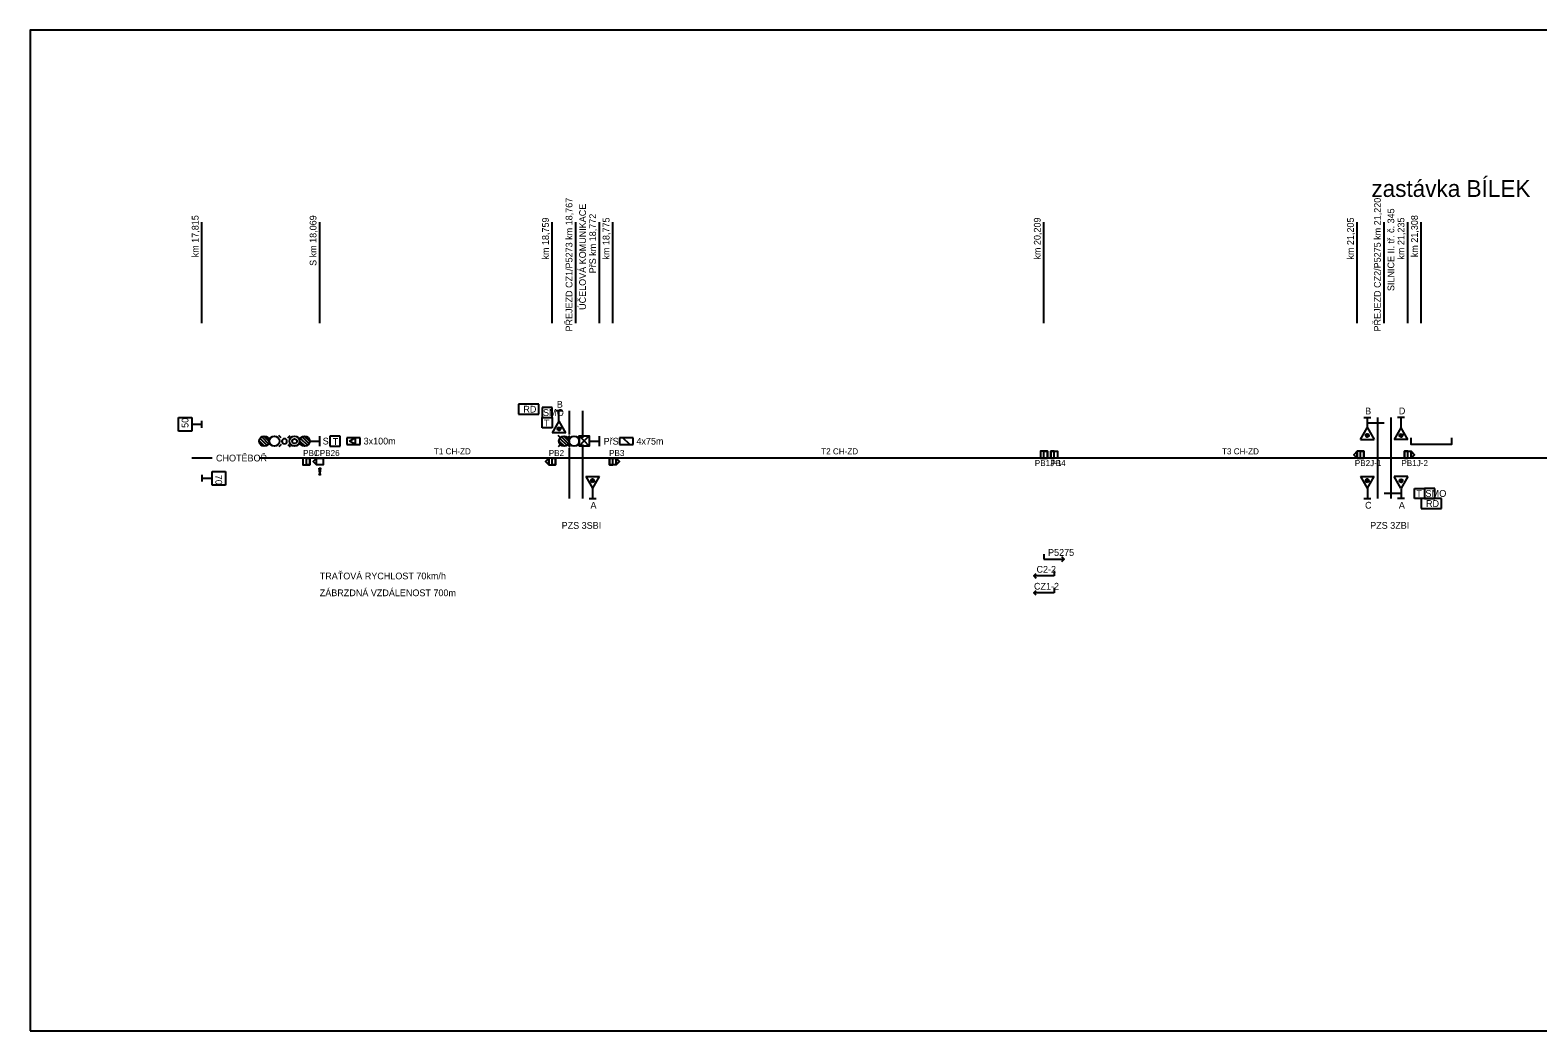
# Model space of a CAD drawing. Extents: x 2343 to 7744, y -5880 to 2050.
# Drawn here: x 4570 to 5017.6, y -5880 to -5583 of the extents above; entities that cross this region are included whole.
import ezdxf

# ---------------------------------------------------------------- set-up
doc = ezdxf.new("R2010")
doc.units = 0
for name, color, linetype in [('LISTY', 7, 'Continuous'), ('NAVRHOVANÉ', 7, 'Continuous'), ('Vrstva 1', 7, 'Continuous'), ('Vrstva 50', 7, 'Continuous'), ('VTO', 7, 'Continuous')]:
    doc.layers.add(name, color=color, linetype=linetype)

# ---------------------------------------------------------------- blocks, each defined once
blk = doc.blocks.new('SB113')
at = {"layer": 'Vrstva 1'}
for points in [[(10, 0), (-10, 0), (-10, -20), (10, -20)], [(0, 0), (10, 0), (10, -20), (0, -20)]]:
    blk.add_lwpolyline(points, close=True, dxfattribs=at)
blk = doc.blocks.new('O10')
at = {"layer": 'Vrstva 1'}
for p, q in [((3, 3), (-3, 3)), ((-3, 3), (-3, 0)), ((-3, 0), (3, 0)), ((3, 0), (3, 3))]:
    blk.add_line(p, q, dxfattribs=at)
blk.add_text('RD', height=2, dxfattribs=at).set_placement((-1.57, 0.503))
blk = doc.blocks.new('O9')
for p, q in [((1.512, 3.012), (-1.488, 3.012)), ((-1.488, 3.012), (-1.488, 0.012)), ((-1.488, 0.012), (1.512, 0.012)), ((1.512, 0.012), (1.512, 3.012))]:
    blk.add_line(p, q)
blk.add_text('T', height=2).set_placement((-0.664, 0.423))
blk = doc.blocks.new('P38')
at = {"layer": 'Vrstva 1'}
for p, q in [((0, 15), (0, 0)), ((0, 0), (60, 0))]:
    blk.add_line(p, q, dxfattribs=at)
blk.add_lwpolyline([(52.9, -7.1), (60, 0), (52.9, 7.1)], dxfattribs=at)
blk = doc.blocks.new('NS14')
for p, q in [((0.1, 18), (-1.5, 16.4)), ((0.8, 17.7), (-1.2, 15.7)), ((1.3, 17.25), (-0.8, 15.2)), ((1.5, 16.6), (-0.1, 15)), ((-1, 11.5), (-1.7, 12.2)), ((-1, 9.5), (-1.7, 8.8)), ((1, 11.5), (1.7, 12.2)), ((1, 9.5), (1.7, 8.8)), ((0.1, 6), (-1.5, 4.4)), ((0.8, 5.7), (-1.2, 3.7)), ((1.3, 5.25), (-0.8, 3.2)), ((1.5, 4.6), (-0.1, 3)), ((-1.5, 0), (1.5, 0)), ((0, 3), (0, 0))]:
    blk.add_line(p, q)
for centre, radius in [((0, 16.5), 1.5), ((0, 13.5), 1.5), ((0, 7.5), 1.5), ((0, 4.5), 1.5), ((0, 7.5), 0.7)]:
    blk.add_circle(centre, radius)
for start, end in [(0, 180), (180, 0)]:
    blk.add_arc((0, 10.5), 0.75, start, end)
blk = doc.blocks.new('NS44')
at = {"layer": 'Vrstva 1'}
blk.add_lwpolyline([(-3.8, 40), (3.7, 40), (0, 10)], close=True, dxfattribs=at)
blk.add_circle((0, 3.7), 3.75, dxfattribs=at)
blk = doc.blocks.new('U7')
at = {"layer": 'Vrstva 1'}
for p, q in [((-1, 4), (-1, 0)), ((1, 4), (-1, 4)), ((-1, 0), (1, 0)), ((-0.971, 1.411), (0.029, 3.143)), ((-0.971, 1.411), (1.029, 1.411)), ((0.029, 3.143), (1.029, 1.411)), ((1, 0), (1, 4))]:
    blk.add_line(p, q, dxfattribs=at)
blk = doc.blocks.new('U3')
at = {"layer": 'Vrstva 1'}
for p, q in [((1, 4), (-1, 4)), ((-1, 4), (-1, 0)), ((-1, 1), (1, 3)), ((-1, 0), (1, 0)), ((1, 0), (1, 4))]:
    blk.add_line(p, q, dxfattribs=at)
blk = doc.blocks.new('NS30')
at = {"layer": 'Vrstva 1'}
for p, q in [((-1.499, 3.001), (0, 1.5)), ((1.499, 3.001), (-1.499, 3.001)), ((-1.499, 0), (0, 1.5)), ((1.499, 0), (-1.499, 0)), ((0, 1.5), (1.499, 3.001)), ((0, 1.5), (1.499, 0))]:
    blk.add_line(p, q, dxfattribs=at)
blk.add_lwpolyline([(-1.499, 3.001), (1.499, 3.001), (1.499, 0), (-1.499, 0)], close=True, dxfattribs=at)

msp = doc.modelspace()

# ---------------------------------------------------------------- linework, layer by layer
for p, q in [((4621, -5670), (4621, -5640)), ((4725, -5670), (4725, -5640)), ((4743, -5670), (4743, -5640)), ((4871, -5670), (4871, -5640)), ((4964, -5670), (4964, -5640)), ((4979, -5670), (4979, -5640)), ((4983, -5670), (4983, -5640)), ((4614, -5702), (4614, -5698)), ((4614, -5698), (4618, -5698)), ((4618, -5698), (4618, -5702)), ((4725, -5695), (4722, -5695)), ((4722, -5695), (4722, -5698)), ((4722, -5698), (4725, -5698)), ((4725, -5698), (4725, -5695)), ((4728, -5696), (4726, -5696)), ((4727, -5699.01), (4727, -5696)), ((4730, -5696), (4730, -5703)), ((4734, -5696), (4734, -5704)), ((4970, -5698), (4970, -5722)), ((4974, -5698), (4974, -5722)), ((4978, -5698), (4976, -5698)), ((4977, -5701.01), (4977, -5698)), ((4618, -5702), (4614, -5702)), ((4621, -5700), (4618, -5700)), ((4621, -5701), (4621, -5699)), ((4726.98, -5699.03), (4725, -5702.52)), ((4729, -5702.52), (4725, -5702.52)), ((4726.52, -5701.26), (4727.05, -5701.79)), ((4726.7, -5700.91), (4727.4, -5701.61)), ((4729, -5702.52), (4727.02, -5699.04)), ((4727.13, -5700.8), (4727.5, -5701.18)), ((4976.98, -5701.03), (4975, -5704.52)), ((4979, -5704.52), (4977.02, -5701.04)), ((4730, -5707), (4730, -5722)), ((4734, -5706), (4734, -5722)), ((4979, -5704.52), (4975, -5704.52)), ((4976.52, -5703.26), (4977.05, -5703.79)), ((4976.7, -5702.91), (4977.4, -5703.61)), ((4977.13, -5702.8), (4977.5, -5703.18)), ((4624, -5710), (4618, -5710)), ((5481, -5710), (4638, -5710)), ((4621, -5715), (4621, -5717)), ((4621, -5716), (4624, -5716)), ((4624, -5714), (4628, -5714)), ((4624, -5718), (4624, -5714)), ((4628, -5714), (4628, -5718)), ((4735, -5715.48), (4739, -5715.48)), ((4735, -5715.48), (4736.98, -5718.96)), ((4737.02, -5718.97), (4739, -5715.48)), ((4965, -5715.48), (4969, -5715.48)), ((4965, -5715.48), (4966.98, -5718.96)), ((4967.02, -5718.97), (4969, -5715.48)), ((4628, -5718), (4624, -5718)), ((4736.87, -5717.2), (4736.5, -5716.82)), ((4737.3, -5717.09), (4736.6, -5716.39)), ((4737.48, -5716.74), (4736.95, -5716.21)), ((4737, -5718.99), (4737, -5722)), ((4966.87, -5717.2), (4966.5, -5716.82)), ((4967.3, -5717.09), (4966.6, -5716.39)), ((4967.48, -5716.74), (4966.95, -5716.21)), ((4967, -5718.99), (4967, -5722)), ((4987, -5719), (4984, -5719)), ((4984, -5719), (4984, -5722)), ((4987, -5722), (4987, -5719)), ((4736, -5722), (4738, -5722)), ((4966, -5722), (4968, -5722)), ((4984, -5722), (4987, -5722))]:
    msp.add_line(p, q)
msp.add_lwpolyline([(4992, -5704), (4992, -5706), (4980, -5706), (4980, -5704)])
for centre, major_axis in [((4727.02, -5701.29), (0, 0.502)), ((4977.02, -5703.29), (0, 0.502)), ((4736.98, -5716.71), (0, -0.502)), ((4966.98, -5716.71), (0, -0.502))]:
    msp.add_ellipse(centre, major_axis=major_axis, ratio=0.996169)
at = {"layer": 'NAVRHOVANÉ'}
for p, q in [((4656, -5670), (4656, -5640)), ((4739, -5670), (4739, -5640)), ((4727.5, -5704), (4726.8, -5703.3)), ((4727.5, -5706), (4726.8, -5706.7)), ((4727, -5704.9), (4728.6, -5706.5)), ((4727.3, -5704.2), (4729.3, -5706.2)), ((4727.75, -5703.7), (4729.8, -5705.8)), ((4728.4, -5703.5), (4730, -5705.1)), ((4729.5, -5704), (4730.2, -5703.3)), ((4729.5, -5706), (4730.2, -5706.7)), ((4736, -5705), (4739, -5705)), ((4739, -5706.5), (4739, -5703.5))]:
    msp.add_line(p, q, dxfattribs=at)
for points in [[(4655, -5710), (4654, -5711), (4655, -5712)], [(4655, -5710), (4657, -5710), (4657, -5712), (4655, -5712)], [(4724, -5710), (4723, -5711), (4724, -5712)], [(4744, -5710), (4745, -5711), (4744, -5712)], [(4964, -5708), (4963, -5709), (4964, -5710)], [(4980, -5708), (4981, -5709), (4980, -5710)]]:
    msp.add_lwpolyline(points, close=True, dxfattribs=at)
for centre in [(4728.5, -5705), (4731.5, -5705)]:
    msp.add_circle(centre, 1.5, dxfattribs=at)
at = {"layer": 'Vrstva 1'}
for p, q in [((4966, -5698), (4968, -5698)), ((4967, -5701), (4967, -5698)), ((4965, -5704.5), (4966.98, -5701.03)), ((4967, -5699.5), (4972, -5699.5)), ((4967.02, -5701.02), (4969, -5704.5)), ((4965, -5704.5), (4969, -5704.5)), ((4966.87, -5702.79), (4966.5, -5703.16)), ((4967.3, -5702.89), (4966.6, -5703.59)), ((4967.48, -5703.24), (4966.95, -5703.77)), ((4976.98, -5718.98), (4975, -5715.5)), ((4979, -5715.5), (4975, -5715.5)), ((4979, -5715.5), (4977.02, -5718.98)), ((4977, -5720.5), (4972, -5720.5)), ((4976.52, -5716.76), (4977.05, -5716.23)), ((4976.7, -5717.11), (4977.4, -5716.41)), ((4977, -5719), (4977, -5722)), ((4977.13, -5717.21), (4977.5, -5716.84)), ((4978, -5722), (4976, -5722))]:
    msp.add_line(p, q, dxfattribs=at)
for centre in [(4966.98, -5703.27), (4977.02, -5716.73)]:
    msp.add_circle(centre, 0.5, dxfattribs=at)
at = {"layer": 'Vrstva 50'}
for p, q in [((4732, -5670), (4732, -5640)), ((4972, -5670), (4972, -5640))]:
    msp.add_line(p, q, dxfattribs=at)
msp.add_lwpolyline([(4570, -5880), (5830, -5880), (5830, -5583), (4570, -5583)], close=True, dxfattribs=at)

# ---------------------------------------------------------------- block references
for p in [(4718, -5697), (4986, -5725)]:
    msp.add_blockref('O10', p)
at = {"xscale": 0.1, "yscale": 0.10000000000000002}
for p in [(4652, -5710), (4725, -5710), (4871, -5708), (4965, -5708)]:
    msp.add_blockref('SB113', p, dxfattribs=at)
at = {"xscale": 0.1, "yscale": -0.10000000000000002, "rotation": 180}
for p in [(4743, -5710), (4874, -5708), (4979, -5708)]:
    msp.add_blockref('SB113', p, dxfattribs=at)
at = {"layer": 'LISTY', "xscale": 0.05, "yscale": 0.05000000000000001}
msp.add_blockref('NS44', (4656, -5715), dxfattribs=at)
at = {"layer": 'NAVRHOVANÉ', "rotation": 90}
for name, p in [('NS14', (4656, -5705)), ('U7', (4668, -5704.97)), ('NS30', (4736, -5704.93)), ('U3', (4749, -5705))]:
    msp.add_blockref(name, p, dxfattribs=at)
at = {"layer": 'NAVRHOVANÉ', "xscale": 0.1, "yscale": 0.10000000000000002}
msp.add_blockref('P38', (4871, -5740), dxfattribs=at)
at = {"layer": 'NAVRHOVANÉ', "xscale": 0.1, "yscale": -0.10000000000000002, "rotation": 180}
for p in [(4874, -5745), (4874, -5750)]:
    msp.add_blockref('P38', p, dxfattribs=at)
at = {"layer": 'VTO', "yscale": -1, "rotation": 180}
for p in [(4723.51, -5701.01), (4982.51, -5722.01)]:
    msp.add_blockref('O9', p, dxfattribs=at)
at = {"layer": 'VTO'}
msp.add_blockref('O9', (4660.49, -5706.51), dxfattribs=at)

# ---------------------------------------------------------------- texts
for s, height, p in [('zastávka BÍLEK', 5, (4968.21, -5632.5)), ('B', 2, (4726.35, -5695.05)), ('SMO', 2.044, (4722.23, -5697.52)), ('B', 2, (4966.35, -5697.05)), ('B', 2, (4966.35, -5697.05)), ('D', 2, (4976.35, -5697)), ('SMO', 2.044, (4984.23, -5721.52)), ('A', 2, (4736.35, -5725)), ('C', 2, (4966.33, -5725)), ('A', 2, (4976.35, -5725)), ('PZS 3SBI', 2, (4727.79, -5731)), ('PZS 3ZBI', 2, (4967.85, -5731)), ('TRAŤOVÁ RYCHLOST 70km/h', 2, (4655.98, -5746)), ('ZÁBRZDNÁ VZDÁLENOST 700m', 2, (4655.99, -5751))]:
    msp.add_text(s, height=height).set_placement(p)
for s, rotation, p in [('km 17,815', 90, (4620, -5650.41)), ('km 18,759', 90, (4724, -5651.09)), ('km 18,775', 90, (4742, -5651.1)), ('km 20,209', 90, (4870, -5651.09)), ('km 21,205', 90, (4963, -5651.1)), ('SILNICE II. tř. č. 345', 90, (4975, -5660.43)), ('km 21,235', 90, (4978, -5651.1)), ('km 21,308', 90, (4982, -5650.39)), ('50', 90, (4617, -5701.04)), ('70', 270, (4625, -5714.96))]:
    msp.add_text(s, height=2, rotation=rotation).set_placement(p)
at = {"layer": 'NAVRHOVANÉ'}
for s, p in [('S km 18,069', (4655, -5652.97)), ('PřS km 18,772', (4738, -5655.17))]:
    msp.add_text(s, height=2, rotation=90, dxfattribs=at).set_placement(p)
for s, height, p in [('S', 2, (4656.86, -5705.97)), ('3x100m', 2, (4669, -5705.97)), ('T1 CH-ZD', 1.8, (4689.86, -5708.9)), ('PřS', 2, (4740.25, -5706)), ('4x75m', 2, (4750, -5706)), ('T2 CH-ZD', 1.8, (4804.86, -5708.9)), ('T3 CH-ZD', 1.8, (4923.86, -5708.9)), ('CHOTĚBOŘ', 2, (4625.18, -5711)), ('PB1', 1.8, (4651.05, -5709.4)), ('CPB26', 1.8, (4654.25, -5709.4)), ('PB2', 1.8, (4723.97, -5709.4)), ('PB3', 1.8, (4741.88, -5709.4)), ('PB1J-1', 1.8, (4868.27, -5712.4)), ('PB4', 1.8, (4872.88, -5712.4)), ('PB2J-1', 1.8, (4963.27, -5712.4)), ('PB1J-2', 1.8, (4977.11, -5712.4)), ('P5275', 2, (4872.21, -5739.02)), ('C2-2', 2, (4868.78, -5744.02)), ('CZ1-2', 2, (4868.03, -5749.04))]:
    msp.add_text(s, height=height, dxfattribs=at).set_placement(p)
at = {"layer": 'Vrstva 50'}
for s, p in [('PŘEJEZD CZ1/P5273 km 18,767', (4731, -5672.44)), ('ÚČELOVÁ KOMUNIKACE', (4735, -5666.02)), ('PŘEJEZD CZ2/P5275 km 21,220', (4971, -5672.43))]:
    msp.add_text(s, height=2, rotation=90, dxfattribs=at).set_placement(p)

doc.saveas('drawing.dxf')
